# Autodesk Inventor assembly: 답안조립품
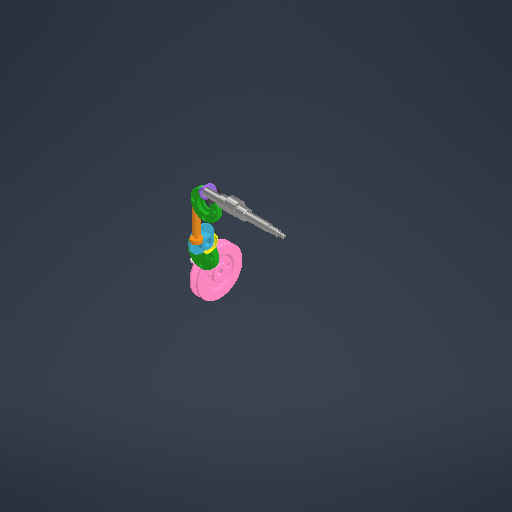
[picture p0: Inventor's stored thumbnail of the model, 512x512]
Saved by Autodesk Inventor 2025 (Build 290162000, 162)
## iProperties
Created: 2025-08
Part Number: 답안조립품
Document SubType Name: Assembly
Designer: infra002
Author: infra002
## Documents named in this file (14)
- C:\Users\infra002\Desktop\750807V1012\답안조립품.iam
- C:\Users\infra002\Desktop\새 폴더\V-벨트풀리\V-벨트풀리.ipt
- C:\Users\infra002\Desktop\새 폴더\너트 M8\너트 M8.ipt
- C:\Users\infra002\Desktop\새 폴더\뒤커버\뒤커버.ipt
- C:\Users\infra002\Desktop\새 폴더\베어링- 6202\베어링- 6202.ipt
- C:\Users\infra002\Desktop\새 폴더\볼트 M4 x 12\볼트 M4 x 12.ipt
- C:\Users\infra002\Desktop\새 폴더\볼트 M4 x 16\볼트 M4 x 16.ipt
- C:\Users\infra002\Desktop\새 폴더\상부커버\상부커버.ipt
- C:\Users\infra002\Desktop\새 폴더\슬라이드\슬라이드.ipt
- C:\Users\infra002\Desktop\새 폴더\앞커버\앞커버.ipt
- C:\Users\infra002\Desktop\새 폴더\오일실 15 30 7\오일실 15 30 7.ipt
- C:\Users\infra002\Desktop\새 폴더\칼라\칼라.ipt
- C:\Users\infra002\Desktop\새 폴더\키 4 x 4 x 12\키 4 x 4 x 12.ipt
- C:\Users\infra002\Desktop\새 폴더\편심축\편심축.ipt
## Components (1 placed, 1 different names)
1. V-벨트풀리:1
